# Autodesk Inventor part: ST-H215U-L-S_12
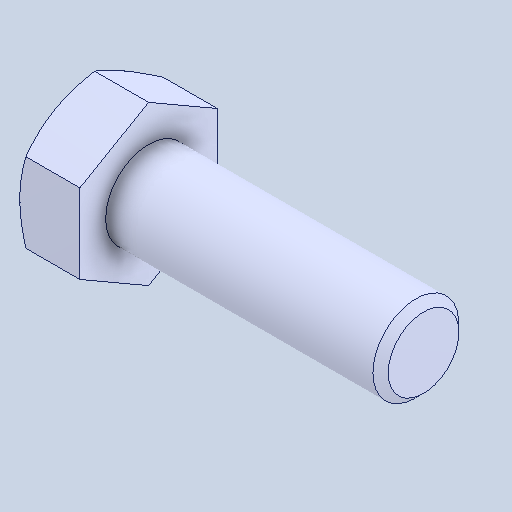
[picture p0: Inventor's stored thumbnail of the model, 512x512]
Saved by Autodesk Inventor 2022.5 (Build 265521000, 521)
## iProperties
Created: 2024-07
Part Number: ST-H215U-L-S_12
Material: 一般
Document SubType Name: Modeling
Designer: ImaoCorp
Density: 1 g/cm^3
Appearance: 既定
Author: ImaoCorp
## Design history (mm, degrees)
feature "ST-H215U-L-S_12"
node "ソリッド1"
